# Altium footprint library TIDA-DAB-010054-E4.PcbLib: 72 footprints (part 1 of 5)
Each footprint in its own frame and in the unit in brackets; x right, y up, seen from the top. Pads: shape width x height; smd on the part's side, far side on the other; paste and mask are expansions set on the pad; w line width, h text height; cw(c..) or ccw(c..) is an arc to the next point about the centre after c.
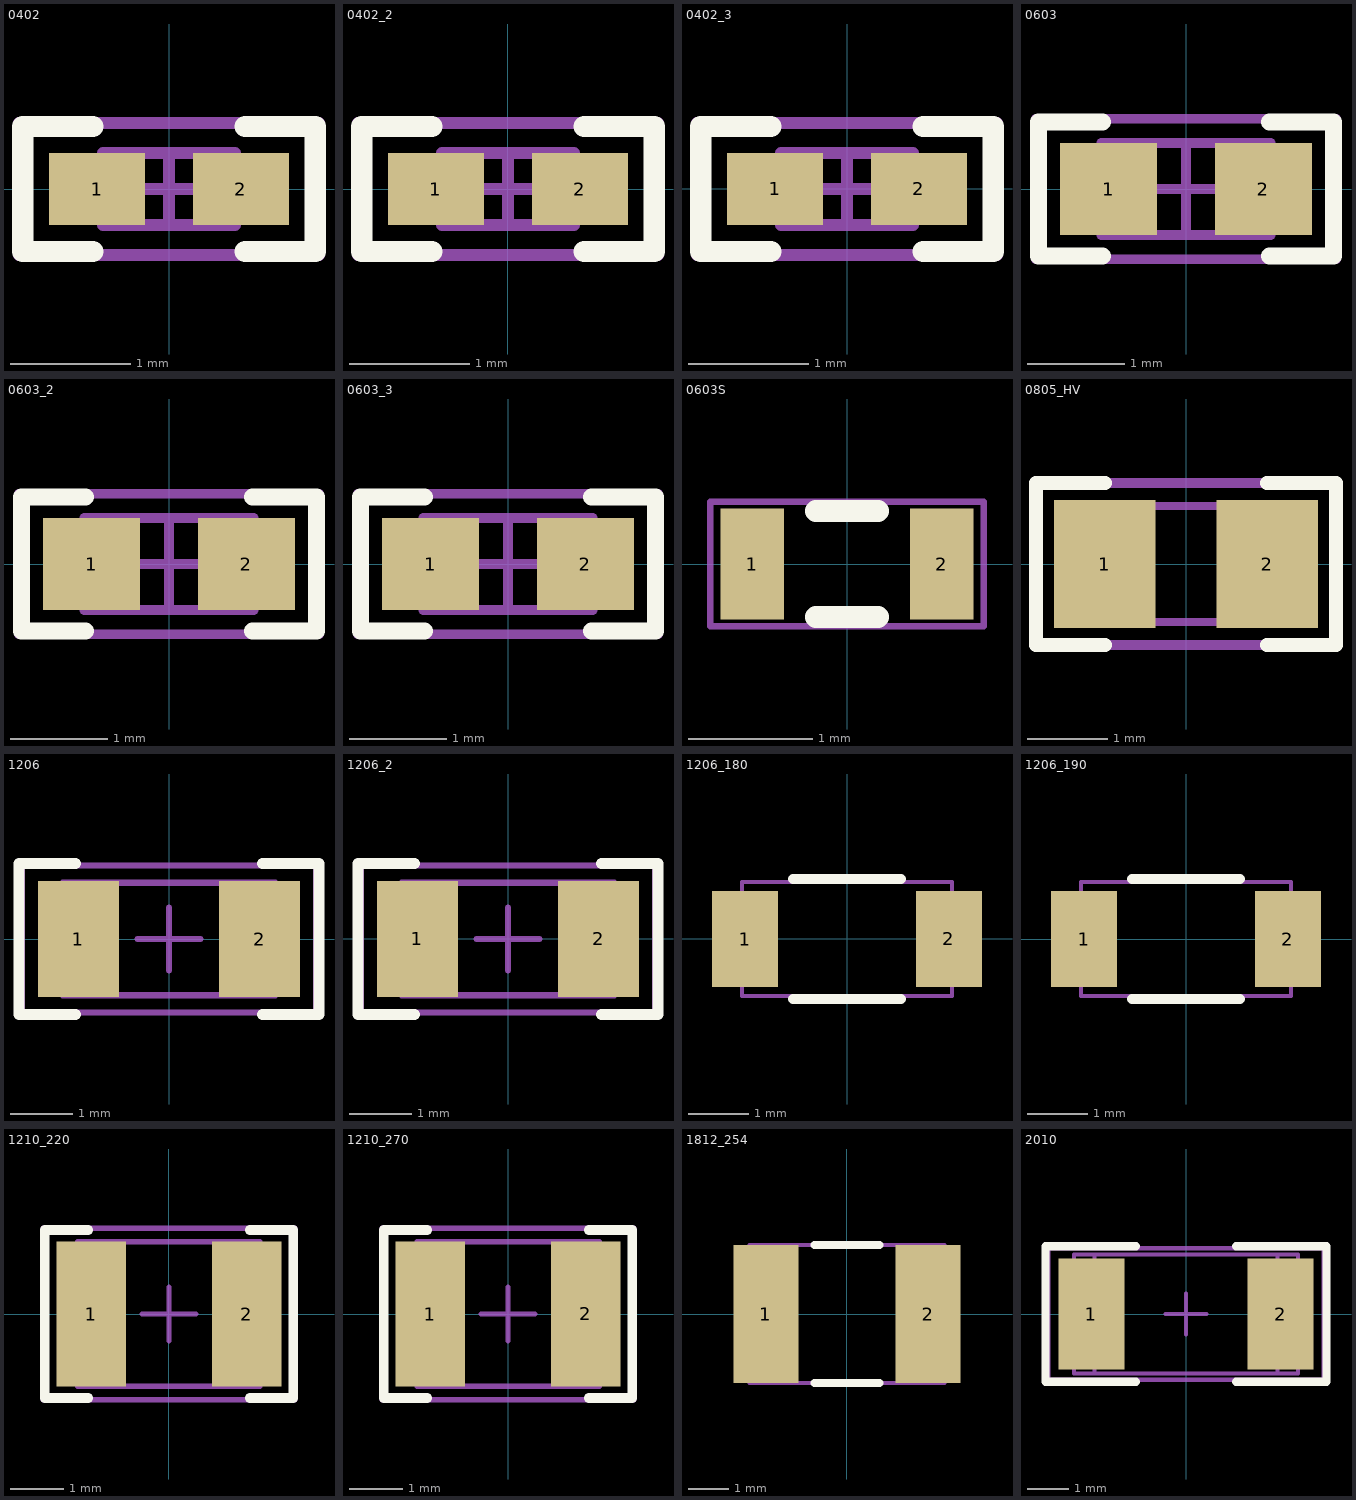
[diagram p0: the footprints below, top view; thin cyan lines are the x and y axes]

## 0402 [mm] "0402 from SM-752 data"
height 0.6
pads (2):
  rect 0.8x0.6 smd: 1(-0.6,0) 2(0.6,0)
Top Overlay:
  lines w0.178: -0.635,-0.521 -1.219,-0.521 -1.219,0.521 -0.635,0.521 ; 0.635,-0.521 1.219,-0.521 1.219,0.521 0.635,0.521
Mechanical 5:
  lines w0.1: -1.25,-0.55 1.25,-0.55 1.25,0.55 -1.25,0.55 -1.25,-0.55
  text ".Designator" at -0.491,-0.211 h0.51
Mechanical 13:
  lines w0.1: -0.35,-0.3 -0.35,0.3 ; 0.35,-0.3 0.35,0.3 ; -0.55,-0.3 -0.55,0.3 0.55,0.3 0.55,-0.3 -0.55,-0.3
Mechanical 15:
  lines w0.1: -0.3,0 0.3,0 ; 0,-0.3 0,0.3 ; -1.25,-0.55 -1.25,0.55 1.25,0.55 1.25,-0.55 -1.25,-0.55
3D body: height 0.6, standoff 0, extent -0.549,-0.299 -0.351,0.299
3D body: height 0.6, standoff 0, extent -0.349,-0.299 0.349,0.299
3D body: height 0.6, standoff 0, extent 0.351,-0.299 0.549,0.299

## 0402_2 [mm]
pads (2):
  rect 0.8x0.6 smd: 1(-0.6,0) 2(0.6,0)
Top Overlay:
  lines w0.178: -0.635,-0.521 -1.219,-0.521 -1.219,0.521 -0.635,0.521 ; 0.635,-0.521 1.219,-0.521 1.219,0.521 0.635,0.521
Mechanical 5:
  lines w0.1: -1.25,-0.55 -1.25,0.55 1.25,0.55 1.25,-0.55 -1.25,-0.55
  text ".Designator" at -0.973,-0.32 h0.51
Mechanical 13:
  lines w0.1: -0.35,-0.3 -0.35,0.3 ; 0.35,-0.3 0.35,0.3 ; -0.55,-0.3 0.55,-0.3 0.55,0.3 -0.55,0.3 -0.55,-0.3
Mechanical 15:
  lines w0.1: -0.3,0 0.3,0 ; 0,-0.3 0,0.3 ; -1.25,-0.55 1.25,-0.55 1.25,0.55 -1.25,0.55 -1.25,-0.55
3D body: height 0.6, standoff 0, extent 0.351,-0.299 0.549,0.299
3D body: height 0.6, standoff 0, extent -0.349,-0.299 0.349,0.299
3D body: height 0.6, standoff 0, extent -0.549,-0.299 -0.351,0.299

## 0402_3 [mm]
pads (2):
  rect 0.8x0.6 smd: 1(-0.6,0) 2(0.6,0)
Top Overlay:
  lines w0.178: -0.635,-0.521 -1.219,-0.521 -1.219,0.521 -0.635,0.521 ; 0.635,-0.521 1.219,-0.521 1.219,0.521 0.635,0.521
Mechanical 5:
  lines w0.1: -1.25,-0.55 1.25,-0.55 1.25,0.55 -1.25,0.55 -1.25,-0.55
  text ".Designator" at -0.6,-0.211 h0.51
Mechanical 13:
  lines w0.1: -0.35,-0.3 -0.35,0.3 ; 0.35,-0.3 0.35,0.3 ; -0.55,-0.3 -0.55,0.3 0.55,0.3 0.55,-0.3 -0.55,-0.3
Mechanical 15:
  lines w0.1: -0.3,0 0.3,0 ; 0,-0.3 0,0.3 ; -1.25,-0.55 -1.25,0.55 1.25,0.55 1.25,-0.55 -1.25,-0.55
3D body: height 0.6, standoff 0, extent -0.549,-0.299 -0.351,0.299
3D body: height 0.6, standoff 0, extent -0.349,-0.299 0.349,0.299
3D body: height 0.6, standoff 0, extent 0.351,-0.299 0.549,0.299

## 0603 [mm] "0603 from SM-752 data"
height 1
pads (2):
  rect 1x0.95 smd: 1(-0.8,0) 2(0.8,0)
Top Overlay:
  lines w0.178: -0.864,-0.691 -1.524,-0.691 -1.524,0.693 -0.864,0.693 ; 0.864,-0.691 1.524,-0.691 1.524,0.693 0.864,0.693
Mechanical 5:
  lines w0.1: -1.55,-0.725 1.55,-0.725 1.55,0.725 -1.55,0.725 -1.55,-0.725
  text ".Designator" at 0.863,0.285 h0.51
Mechanical 13:
  lines w0.1: -0.55,-0.475 -0.55,0.475 ; 0.55,-0.475 0.55,0.475 ; -0.875,-0.475 -0.875,0.475 0.875,0.475 0.875,-0.475 -0.875,-0.475
Mechanical 15:
  lines w0.1: -0.475,0 0.475,0 ; 0,-0.475 0,0.475 ; -1.55,-0.725 -1.55,0.725 1.55,0.725 1.55,-0.725 -1.55,-0.725
3D body: height 1, standoff 0, extent 0.551,-0.474 0.874,0.474
3D body: height 1, standoff 0, extent -0.549,-0.474 0.549,0.474
3D body: height 1, standoff 0, extent -0.874,-0.474 -0.551,0.474

## 0603_2 [mm]
pads (2):
  rect 1x0.95 smd: 1(-0.8,0) 2(0.8,0)
Top Overlay:
  lines w0.178: -0.864,-0.691 -1.524,-0.691 -1.524,0.693 -0.864,0.693 ; 0.864,-0.691 1.524,-0.691 1.524,0.693 0.864,0.693
Mechanical 5:
  lines w0.1: -1.55,-0.725 -1.55,0.725 1.55,0.725 1.55,-0.725 -1.55,-0.725
  text ".Designator" at 0.763,0.282 h0.51
Mechanical 13:
  lines w0.1: -0.55,-0.475 -0.55,0.475 ; 0.55,-0.475 0.55,0.475 ; -0.875,-0.475 0.875,-0.475 0.875,0.475 -0.875,0.475 -0.875,-0.475
Mechanical 15:
  lines w0.1: -0.475,0 0.475,0 ; 0,-0.475 0,0.475 ; -1.55,-0.725 1.55,-0.725 1.55,0.725 -1.55,0.725 -1.55,-0.725
3D body: height 1, standoff 0, extent -0.874,-0.474 -0.551,0.474
3D body: height 1, standoff 0, extent -0.549,-0.474 0.549,0.474
3D body: height 1, standoff 0, extent 0.551,-0.474 0.874,0.474

## 0603_3 [mm]
pads (2):
  rect 1x0.95 smd: 1(-0.8,0) 2(0.8,0)
Top Overlay:
  lines w0.178: -0.864,-0.691 -1.524,-0.691 -1.524,0.693 -0.864,0.693 ; 0.864,-0.691 1.524,-0.691 1.524,0.693 0.864,0.693
Mechanical 5:
  lines w0.1: -1.55,-0.725 1.55,-0.725 1.55,0.725 -1.55,0.725 -1.55,-0.725
  text ".Designator" at -0.818,-0.254 h0.51
Mechanical 13:
  lines w0.1: -0.55,-0.475 -0.55,0.475 ; 0.55,-0.475 0.55,0.475 ; -0.875,-0.475 -0.875,0.475 0.875,0.475 0.875,-0.475 -0.875,-0.475
Mechanical 15:
  lines w0.1: -0.475,0 0.475,0 ; 0,-0.475 0,0.475 ; -1.55,-0.725 -1.55,0.725 1.55,0.725 1.55,-0.725 -1.55,-0.725
3D body: height 1, standoff 0, extent 0.551,-0.474 0.874,0.474
3D body: height 1, standoff 0, extent -0.549,-0.474 0.549,0.474
3D body: height 1, standoff 0, extent -0.874,-0.474 -0.551,0.474

## 0603S [mil]
height 39.37
pads (2):
  rect 20x35 smd: 1(-30,0) 2(30,0)
Top Overlay:
  lines w7: -9.84,-16.73 9.84,-16.73 ; -9.84,16.73 9.84,16.73
Mechanical 5:
  lines w1.97: -43.31,-19.68 -43.31,19.68 43.31,19.68 43.31,-19.68 -43.31,-19.68
  text ".Designator" at -32.48,-8.86 h20
3D body: height 39.37, standoff 0, extent 21.67,-18.68 34.43,18.68
3D body: height 39.37, standoff 0, extent -21.63,-18.68 21.63,18.68
3D body: height 39.37, standoff 0, extent -34.43,-18.68 -21.67,18.68

## 0805_HV [mil] "0805 with 30mil clearance between pads"
height 57.09
pads (2):
  rect 50x63 smd: 1(-40,0) 2(40,0)
Top Overlay:
  lines w7: -40,-40 -74,-40 -74,0 -74,40 -40,40 ; 40,-40 74,-40 74,0 74,40 40,40
Mechanical 5:
  lines w5: -74,-40 -74,40 74,40 74,-40 -74,-40
  text ".Designator" at -25.59,-4.15 h20
Mechanical 13:
  lines w3.94: -25.59,-28.54 -25.59,28.54 ; 25.59,-28.54 25.59,28.54 ; -43.31,-28.54 -43.31,28.54 43.31,28.54 43.31,-28.54 -43.31,-28.54
3D body: height 57.09, standoff 0, extent 25.61,-28.52 43.29,28.52
3D body: height 57.09, standoff 0, extent -25.57,-28.52 25.57,28.52
3D body: height 57.09, standoff 0, extent -43.29,-28.52 -25.61,28.52

## 1206 [mm] "1206 from SM-752 data"
height 1.35
pads (2):
  rect 1.3x1.85 smd: 1(-1.45,0) 2(1.45,0)
Top Overlay:
  lines w0.178: -1.5,-1.21 -2.4,-1.21 -2.4,1.21 -1.5,1.21 ; 1.5,-1.21 2.4,-1.21 2.4,1.21 1.5,1.21
Mechanical 5:
  lines w0.1: -1.7,-0.9 1.7,-0.9 1.7,0.9 -1.7,0.9 -1.7,-0.9
  text ".Designator" at 0.406,0.254 h0.51
Mechanical 13:
  lines w0.1: -1.2,-0.9 -1.2,0.9 ; 1.2,-0.9 1.2,0.9 ; -1.7,-0.9 1.7,-0.9 1.7,0.9 -1.7,0.9 -1.7,-0.9
Mechanical 15:
  lines w0.1: -0.5,0 0.5,0 ; 0,-0.5 0,0.5 ; -2.35,-1.175 2.35,-1.175 2.35,1.175 -2.35,1.175 -2.35,-1.175
3D body: height 1.35, standoff 0, extent -1.699,-0.899 -1.201,0.899
3D body: height 1.35, standoff 0, extent -1.199,-0.899 1.199,0.899
3D body: height 1.35, standoff 0, extent 1.201,-0.899 1.699,0.899

## 1206_2 [mm]
pads (2):
  rect 1.3x1.85 smd: 1(-1.45,0) 2(1.45,0)
Top Overlay:
  lines w0.178: -1.5,-1.21 -2.4,-1.21 -2.4,1.21 -1.5,1.21 ; 1.5,-1.21 2.4,-1.21 2.4,1.21 1.5,1.21
Mechanical 5:
  lines w0.1: -1.7,-0.9 1.7,-0.9 1.7,0.9 -1.7,0.9 -1.7,-0.9
  text ".Designator" at -0.61,-0.184 h0.51
Mechanical 13:
  lines w0.1: -1.2,-0.9 -1.2,0.9 ; 1.2,-0.9 1.2,0.9 ; -1.7,-0.9 1.7,-0.9 1.7,0.9 -1.7,0.9 -1.7,-0.9
Mechanical 15:
  lines w0.1: -0.5,0 0.5,0 ; 0,-0.5 0,0.5 ; -2.35,-1.175 2.35,-1.175 2.35,1.175 -2.35,1.175 -2.35,-1.175
3D body: height 1.35, standoff 0, extent -1.699,-0.899 -1.201,0.899
3D body: height 1.35, standoff 0, extent -1.199,-0.899 1.199,0.899
3D body: height 1.35, standoff 0, extent 1.201,-0.899 1.699,0.899

## 1206_180 [mm] "1206_180"
height 1.8
pads (2):
  rect 1.1x1.6 smd: 1(-1.7,0) 2(1.7,0)
Top Overlay:
  lines w0.17: -0.9,-1 0.9,-1 ; -0.9,1 0.9,1
Mechanical 5:
  lines w0.07: -1.75,-0.95 -1.75,0.95 1.75,0.95 1.75,-0.95 -1.75,-0.95
  text ".Designator" at -0.521,-0.313 h0.51
3D body: height 1.8, standoff 0, extent 1.301,-0.949 1.749,0.949
3D body: height 1.8, standoff 0, extent -1.299,-0.949 1.299,0.949
3D body: height 1.8, standoff 0, extent -1.749,-0.949 -1.301,0.949

## 1206_190 [mm] "1206_190"
height 1.9
pads (2):
  rect 1.1x1.6 smd: 1(-1.7,0) 2(1.7,0)
Top Overlay:
  lines w0.17: -0.9,-1 0.9,-1 ; -0.9,1 0.9,1
Mechanical 5:
  lines w0.07: -1.75,-0.95 -1.75,0.95 1.75,0.95 1.75,-0.95 -1.75,-0.95
  text ".Designator" at 0.904,0.45 h0.51
3D body: height 1.9, standoff 0, extent 1.301,-0.949 1.749,0.949
3D body: height 1.9, standoff 0, extent -1.299,-0.949 1.299,0.949
3D body: height 1.9, standoff 0, extent -1.749,-0.949 -1.301,0.949

## 1210_220 [mm] "1210"
height 2.2
pads (2):
  rect 1.3x2.7 smd: 1(-1.45,0) 2(1.45,0)
Top Overlay:
  lines w0.178: -1.511,-1.568 -2.316,-1.568 -2.316,1.568 -1.511,1.568 ; 1.511,-1.568 2.316,-1.568 2.316,1.568 1.511,1.568
Mechanical 5:
  lines w0.1: -1.7,-1.35 -1.7,1.35 1.7,1.35 1.7,-1.35 -1.7,-1.35
  text ".Designator" at -0.627,-0.186 h0.51
Mechanical 13:
  lines w0.1: -1.2,-1.35 -1.2,1.35 ; 1.2,-1.35 1.2,1.35 ; -1.7,-1.35 1.7,-1.35 1.7,1.35 -1.7,1.35 -1.7,-1.35
Mechanical 15:
  lines w0.1: -0.5,0 0.5,0 ; 0,-0.5 0,0.5 ; -2.35,-1.6 2.35,-1.6 2.35,1.6 -2.35,1.6 -2.35,-1.6
3D body: height 2.2, standoff 0, extent 1.201,-1.349 1.699,1.349
3D body: height 2.2, standoff 0, extent -1.199,-1.349 1.199,1.349
3D body: height 2.2, standoff 0, extent -1.699,-1.349 -1.201,1.349

## 1210_270 [mm] "1210"
height 2.7
pads (2):
  rect 1.3x2.7 smd: 1(-1.45,0) 2(1.45,0)
Top Overlay:
  lines w0.178: -1.511,-1.568 -2.316,-1.568 -2.316,1.568 -1.511,1.568 ; 1.511,-1.568 2.316,-1.568 2.316,1.568 1.511,1.568
Mechanical 5:
  lines w0.1: -1.7,-1.35 -1.7,1.35 1.7,1.35 1.7,-1.35 -1.7,-1.35
  text ".Designator" at 0.61,0.334 h0.51
Mechanical 13:
  lines w0.1: -1.2,-1.35 -1.2,1.35 ; 1.2,-1.35 1.2,1.35 ; -1.7,-1.35 1.7,-1.35 1.7,1.35 -1.7,1.35 -1.7,-1.35
Mechanical 15:
  lines w0.1: -0.5,0 0.5,0 ; 0,-0.5 0,0.5 ; -2.35,-1.6 2.35,-1.6 2.35,1.6 -2.35,1.6 -2.35,-1.6
3D body: height 2.7, standoff 0, extent 1.201,-1.349 1.699,1.349
3D body: height 2.7, standoff 0, extent -1.199,-1.349 1.199,1.349
3D body: height 2.7, standoff 0, extent -1.699,-1.349 -1.201,1.349

## 1812_254 [mm] "SMD, 2-Leads, Body 4.8x3.4mm"
height 2.54
pads (2):
  rect 1.6x3.4 smd: 1(-2,0) 2(2,0)
Top Overlay:
  lines w0.2: -0.8,-1.7 0.8,-1.7 ; -0.8,1.7 0.8,1.7
Mechanical 5:
  lines w0.1: -1.9,-1.7 -1.9,1.7 ; 1.9,-1.7 1.9,1.7 ; -2.4,-1.7 2.4,-1.7 2.4,1.7 -2.4,1.7 -2.4,-1.7
  text ".Designator" at 0.319,-0.867 h0.51
3D body: height 2.54, standoff 0, extent -2.399,-1.699 -1.901,1.699
3D body: height 2.54, standoff 0, extent -1.899,-1.699 1.899,1.699
3D body: height 2.54, standoff 0, extent 1.901,-1.699 2.399,1.699

## 2010 [mm] "Chip Capacitor, Body 5.08x2.54mm, IPC Medium Density"
height 1.66
pads (2):
  rect 1.6x2.7 smd: 1(-2.3,0) 2(2.3,0)
Top Overlay:
  lines w0.2: -1.219,-1.65 -3.419,-1.65 -3.419,1.65 -1.219,1.65 ; 1.219,-1.65 3.419,-1.65 3.419,1.65 1.219,1.65
Mechanical 5:
  lines w0.1: -2.73,-1.45 2.73,-1.45 2.73,1.45 -2.73,1.45 -2.73,-1.45
  text ".Designator" at 0.833,0.163 h0.51
Mechanical 13:
  lines w0.1: -2.23,-1.45 -2.23,1.45 ; 2.23,-1.45 2.23,1.45 ; -2.73,-1.45 -2.73,1.45 2.73,1.45 2.73,-1.45 -2.73,-1.45
Mechanical 15:
  lines w0.1: -0.5,0 0.5,0 ; 0,-0.5 0,0.5 ; -3.35,-1.6 -3.35,1.6 3.35,1.6 3.35,-1.6 -3.35,-1.6
3D body: height 1.66, standoff 0, extent 2.231,-1.449 2.729,1.449
3D body: height 1.66, standoff 0, extent -2.229,-1.449 2.229,1.449
3D body: height 1.66, standoff 0, extent -2.729,-1.449 -2.231,1.449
